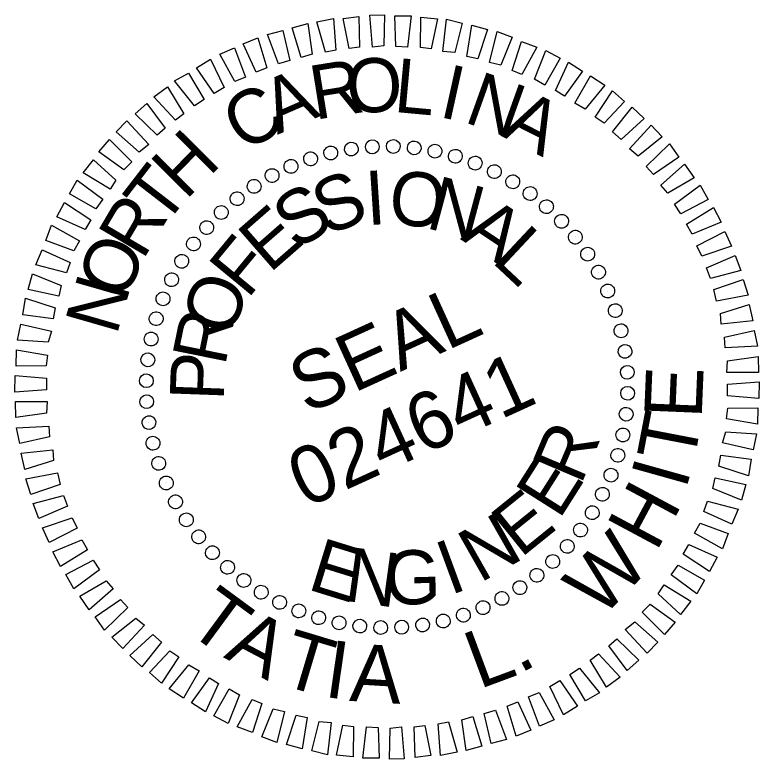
# Model space of a CAD drawing. Extents: x 2249019 to 2251039, y 663030 to 664799.
# Drawn here: x 2250809.3 to 2250886.9, y 664679.9 to 664757.5 of the extents above; entities that cross this region are included whole.
import ezdxf

# ---------------------------------------------------------------- set-up
doc = ezdxf.new("R2010")
doc.units = 0
doc.layers.add('Sheet Professional Seal CELL', color=7, linetype='Continuous')

msp = doc.modelspace()

# ---------------------------------------------------------------- linework, layer by layer
at = {"layer": 'Sheet Professional Seal CELL'}
for p, q in [((2250844.359, 664743.503), (2250844.359, 664743.503)), ((2250846.56, 664743.738), (2250846.56, 664743.738)), ((2250848.753, 664743.749), (2250848.753, 664743.749)), ((2250850.942, 664743.648), (2250850.942, 664743.648)), ((2250853.099, 664743.257), (2250853.099, 664743.257)), ((2250840.16, 664742.468), (2250840.16, 664742.468)), ((2250842.261, 664743.042), (2250842.261, 664743.042)), ((2250855.251, 664742.755), (2250855.251, 664742.755)), ((2250838.096, 664741.692), (2250838.096, 664741.692)), ((2250857.284, 664742.033), (2250857.284, 664742.033)), ((2250859.333, 664741.154), (2250859.333, 664741.154)), ((2250836.115, 664740.733), (2250836.115, 664740.733)), ((2250834.283, 664739.568), (2250834.283, 664739.568)), ((2250861.196, 664740.081), (2250861.196, 664740.081)), ((2250863.031, 664738.829), (2250863.031, 664738.829)), ((2250832.447, 664738.292), (2250832.447, 664738.292)), ((2250864.75, 664737.47), (2250864.75, 664737.47)), ((2250830.786, 664736.875), (2250830.786, 664736.875)), ((2250866.308, 664735.982), (2250866.308, 664735.982)), ((2250829.298, 664735.317), (2250829.298, 664735.317)), ((2250867.725, 664734.32), (2250867.725, 664734.32)), ((2250827.938, 664733.598), (2250827.938, 664733.598)), ((2250869.001, 664732.484), (2250869.001, 664732.484)), ((2250826.687, 664731.763), (2250826.687, 664731.763)), ((2250870.166, 664730.652), (2250870.166, 664730.652)), ((2250825.613, 664729.9), (2250825.613, 664729.9)), ((2250871.125, 664728.671), (2250871.125, 664728.671)), ((2250824.734, 664727.851), (2250824.734, 664727.851)), ((2250871.901, 664726.607), (2250871.901, 664726.607)), ((2250824.012, 664725.818), (2250824.012, 664725.818)), ((2250872.474, 664724.506), (2250872.474, 664724.506)), ((2250823.51, 664723.666), (2250823.51, 664723.666)), ((2250872.936, 664722.409), (2250872.936, 664722.409)), ((2250823.12, 664721.509), (2250823.12, 664721.509)), ((2250873.171, 664720.207), (2250873.171, 664720.207)), ((2250823.019, 664719.32), (2250823.019, 664719.32)), ((2250848.1, 664718.667), (2250848.1, 664718.667)), ((2250873.182, 664718.014), (2250873.182, 664718.014)), ((2250823.03, 664717.127), (2250823.03, 664717.127)), ((2250873.081, 664715.825), (2250873.081, 664715.825)), ((2250823.264, 664714.926), (2250823.264, 664714.926)), ((2250872.69, 664713.669), (2250872.69, 664713.669)), ((2250823.726, 664712.828), (2250823.726, 664712.828)), ((2250872.188, 664711.516), (2250872.188, 664711.516)), ((2250824.299, 664710.727), (2250824.299, 664710.727)), ((2250871.466, 664709.484), (2250871.466, 664709.484)), ((2250825.076, 664708.663), (2250825.076, 664708.663)), ((2250870.587, 664707.434), (2250870.587, 664707.434)), ((2250826.034, 664706.682), (2250826.034, 664706.682)), ((2250869.514, 664705.571), (2250869.514, 664705.571)), ((2250827.199, 664704.85), (2250827.199, 664704.85)), ((2250868.262, 664703.736), (2250868.262, 664703.736)), ((2250828.476, 664703.014), (2250828.476, 664703.014)), ((2250829.893, 664701.353), (2250829.893, 664701.353)), ((2250866.903, 664702.017), (2250866.903, 664702.017)), ((2250831.45, 664699.865), (2250831.45, 664699.865)), ((2250865.415, 664700.46), (2250865.415, 664700.46)), ((2250863.753, 664699.043), (2250863.753, 664699.043)), ((2250833.169, 664698.505), (2250833.169, 664698.505)), ((2250861.917, 664697.766), (2250861.917, 664697.766)), ((2250835.004, 664697.254), (2250835.004, 664697.254)), ((2250836.867, 664696.18), (2250836.867, 664696.18)), ((2250860.085, 664696.601), (2250860.085, 664696.601)), ((2250838.917, 664695.301), (2250838.917, 664695.301)), ((2250858.104, 664695.643), (2250858.104, 664695.643)), ((2250840.949, 664694.579), (2250840.949, 664694.579)), ((2250856.04, 664694.866), (2250856.04, 664694.866)), ((2250843.102, 664694.077), (2250843.102, 664694.077)), ((2250845.258, 664693.687), (2250845.258, 664693.687)), ((2250849.64, 664693.597), (2250849.64, 664693.597)), ((2250851.842, 664693.831), (2250851.842, 664693.831)), ((2250853.939, 664694.293), (2250853.939, 664694.293)), ((2250847.447, 664693.586), (2250847.447, 664693.586))]:
    msp.add_line(p, q, dxfattribs=at)
for points in [[(2250844.152, 664753.96), (2250843.548, 664757.092), (2250845.166, 664757.28), (2250845.252, 664754.077)], [(2250846.572, 664754.075), (2250846.312, 664757.418), (2250847.835, 664757.453), (2250847.764, 664754.233)], [(2250849.014, 664754.144), (2250848.927, 664757.346), (2250850.628, 664757.353), (2250850.243, 664754.1)], [(2250851.584, 664754.052), (2250851.629, 664757.205), (2250853.347, 664757.054), (2250852.697, 664753.9)], [(2250839.15, 664752.998), (2250838.232, 664756.096), (2250839.837, 664756.553), (2250840.304, 664753.359)], [(2250841.698, 664753.556), (2250840.805, 664756.72), (2250842.518, 664757.061), (2250842.757, 664753.764)], [(2250853.918, 664753.632), (2250854.307, 664756.997), (2250855.925, 664756.581), (2250855.168, 664753.543)], [(2250836.8, 664752.366), (2250835.634, 664755.406), (2250837.26, 664755.818), (2250837.975, 664752.682)], [(2250856.405, 664753.118), (2250856.948, 664756.388), (2250858.587, 664755.926), (2250857.56, 664752.875)], [(2250858.777, 664752.496), (2250859.564, 664755.712), (2250861.154, 664755.118), (2250859.953, 664752.208)], [(2250834.463, 664751.466), (2250833.115, 664754.423), (2250834.637, 664755.062), (2250835.576, 664751.918)], [(2250861.141, 664751.65), (2250862.122, 664754.681), (2250863.712, 664754.087), (2250862.155, 664751.234)], [(2250832.259, 664750.515), (2250830.683, 664753.369), (2250832.205, 664754.008), (2250833.372, 664750.968)], [(2250863.48, 664750.739), (2250864.639, 664753.74), (2250866.155, 664752.947), (2250864.532, 664750.119)], [(2250830.088, 664749.251), (2250828.26, 664751.934), (2250829.724, 664752.821), (2250831.118, 664749.885)], [(2250865.654, 664749.587), (2250867.012, 664752.514), (2250868.478, 664751.589), (2250866.594, 664748.971)], [(2250828.029, 664747.982), (2250825.973, 664750.562), (2250827.412, 664751.383), (2250829.058, 664748.616)], [(2250867.687, 664748.261), (2250869.31, 664751.089), (2250870.797, 664750.118), (2250868.739, 664747.641)], [(2250826.073, 664746.486), (2250823.811, 664748.916), (2250825.213, 664749.94), (2250826.925, 664747.149)], [(2250869.783, 664746.799), (2250871.605, 664749.553), (2250872.839, 664748.412), (2250870.723, 664746.183)], [(2250824.159, 664744.899), (2250821.868, 664747.151), (2250823.092, 664748.204), (2250824.969, 664745.653)], [(2250871.585, 664745.257), (2250873.647, 664747.846), (2250874.902, 664746.66), (2250872.496, 664744.464)], [(2250822.262, 664743.154), (2250819.876, 664745.254), (2250820.992, 664746.422), (2250823.275, 664743.946)], [(2250873.379, 664743.492), (2250875.614, 664745.941), (2250876.758, 664744.759), (2250874.269, 664742.744)], [(2250820.696, 664741.286), (2250818.078, 664743.17), (2250819.198, 664744.45), (2250821.51, 664742.152)], [(2250875.102, 664741.641), (2250877.537, 664744.015), (2250878.494, 664742.638), (2250875.856, 664740.83)], [(2250819.238, 664739.302), (2250816.434, 664740.991), (2250817.513, 664742.362), (2250819.853, 664740.242)], [(2250876.644, 664739.706), (2250879.116, 664741.877), (2250880.094, 664740.455), (2250877.353, 664738.875)], [(2250817.754, 664737.252), (2250815.013, 664738.805), (2250815.802, 664740.209), (2250818.506, 664738.254)], [(2250878.049, 664737.709), (2250880.716, 664739.694), (2250881.558, 664738.21), (2250878.729, 664736.7)], [(2250816.648, 664735.099), (2250813.696, 664736.391), (2250814.489, 664737.906), (2250817.243, 664736.085)], [(2250879.318, 664735.65), (2250882.109, 664737.362), (2250882.905, 664735.857), (2250879.907, 664734.599)], [(2250815.471, 664732.859), (2250812.557, 664733.948), (2250813.151, 664735.538), (2250816.045, 664733.89)], [(2250880.401, 664733.396), (2250883.295, 664734.881), (2250884.001, 664733.334), (2250880.898, 664732.304)], [(2250814.696, 664730.582), (2250811.525, 664731.389), (2250812.186, 664732.954), (2250815.092, 664731.642)], [(2250881.392, 664731.1), (2250884.391, 664732.358), (2250884.984, 664730.815), (2250881.799, 664729.967)], [(2250813.892, 664728.127), (2250810.717, 664728.823), (2250811.179, 664730.462), (2250814.156, 664729.237)], [(2250882.161, 664728.813), (2250885.197, 664729.868), (2250885.72, 664728.238), (2250882.431, 664727.617)], [(2250813.316, 664725.776), (2250810.154, 664726.203), (2250810.416, 664727.916), (2250813.513, 664726.91)], [(2250882.855, 664726.327), (2250885.841, 664727.249), (2250886.228, 664725.557), (2250882.926, 664725.205)], [(2250812.781, 664723.334), (2250809.611, 664723.537), (2250809.94, 664725.226), (2250813.135, 664724.485)], [(2250883.259, 664723.873), (2250886.349, 664724.568), (2250886.715, 664722.922), (2250883.331, 664722.752)], [(2250812.581, 664720.88), (2250809.469, 664720.835), (2250809.508, 664722.556), (2250812.733, 664721.993)], [(2250883.572, 664721.379), (2250886.766, 664721.846), (2250886.818, 664720.166), (2250883.507, 664720.195)], [(2250812.625, 664718.372), (2250809.327, 664718.133), (2250809.367, 664719.854), (2250812.624, 664719.581)], [(2250883.575, 664718.962), (2250886.873, 664719.202), (2250886.834, 664717.48), (2250883.577, 664717.754)], [(2250812.628, 664715.956), (2250809.434, 664715.489), (2250809.382, 664717.169), (2250812.693, 664717.139)], [(2250883.619, 664716.454), (2250886.731, 664716.499), (2250886.692, 664714.778), (2250883.468, 664715.341)], [(2250812.941, 664713.461), (2250809.851, 664712.766), (2250809.485, 664714.413), (2250812.87, 664714.582)], [(2250883.42, 664714), (2250886.59, 664713.797), (2250886.261, 664712.108), (2250883.065, 664712.849)], [(2250813.346, 664711.008), (2250810.359, 664710.085), (2250809.972, 664711.777), (2250813.274, 664712.129)], [(2250882.885, 664711.558), (2250886.047, 664711.132), (2250885.784, 664709.418), (2250882.687, 664710.424)], [(2250814.04, 664708.522), (2250811.004, 664707.467), (2250810.48, 664709.097), (2250813.769, 664709.717)], [(2250882.308, 664709.207), (2250885.483, 664708.512), (2250885.021, 664706.872), (2250882.045, 664708.098)], [(2250814.808, 664706.234), (2250811.809, 664704.977), (2250811.216, 664706.519), (2250814.401, 664707.367)], [(2250881.504, 664706.752), (2250884.675, 664705.945), (2250884.015, 664704.38), (2250881.108, 664705.692)], [(2250815.8, 664703.939), (2250812.905, 664702.454), (2250812.199, 664704.001), (2250815.302, 664705.031)], [(2250880.729, 664704.475), (2250883.643, 664703.386), (2250883.049, 664701.797), (2250880.155, 664703.444)], [(2250816.882, 664701.685), (2250814.091, 664699.972), (2250813.295, 664701.478), (2250816.294, 664702.735)], [(2250879.552, 664702.235), (2250882.504, 664700.944), (2250881.711, 664699.428), (2250878.958, 664701.25)], [(2250818.151, 664699.625), (2250815.484, 664697.64), (2250814.643, 664699.125), (2250817.471, 664700.634)], [(2250878.446, 664700.082), (2250881.187, 664698.53), (2250880.398, 664697.126), (2250877.694, 664699.08)], [(2250819.556, 664697.629), (2250817.084, 664695.457), (2250816.106, 664696.88), (2250818.848, 664698.459)], [(2250876.963, 664698.032), (2250879.766, 664696.343), (2250878.688, 664694.972), (2250876.347, 664697.092)], [(2250821.098, 664695.694), (2250818.663, 664693.32), (2250817.706, 664694.697), (2250820.344, 664696.504)], [(2250875.504, 664696.048), (2250878.122, 664694.164), (2250877.002, 664692.884), (2250874.69, 664695.182)], [(2250822.822, 664693.842), (2250820.586, 664691.394), (2250819.442, 664692.576), (2250821.931, 664694.59)], [(2250873.938, 664694.18), (2250876.324, 664692.081), (2250875.208, 664690.913), (2250872.925, 664693.389)], [(2250824.615, 664692.077), (2250822.554, 664689.488), (2250821.298, 664690.675), (2250823.704, 664692.871)], [(2250872.041, 664692.436), (2250874.332, 664690.183), (2250873.108, 664689.131), (2250871.231, 664691.682)], [(2250826.417, 664690.536), (2250824.596, 664687.782), (2250823.361, 664688.922), (2250825.477, 664691.151)], [(2250870.127, 664690.849), (2250872.389, 664688.418), (2250870.988, 664687.394), (2250869.275, 664690.186)], [(2250828.513, 664689.073), (2250826.89, 664686.245), (2250825.403, 664687.216), (2250827.461, 664689.693)], [(2250868.171, 664689.352), (2250870.227, 664686.773), (2250868.788, 664685.952), (2250867.142, 664688.718)], [(2250830.546, 664687.748), (2250829.188, 664684.82), (2250827.722, 664685.746), (2250829.606, 664688.363)], [(2250866.112, 664688.084), (2250867.94, 664685.4), (2250866.476, 664684.513), (2250865.083, 664687.449)], [(2250832.72, 664686.596), (2250831.561, 664683.594), (2250830.045, 664684.387), (2250831.668, 664687.215)], [(2250863.941, 664686.819), (2250865.517, 664683.966), (2250863.995, 664683.327), (2250862.829, 664686.367)], [(2250835.059, 664685.684), (2250834.078, 664682.654), (2250832.488, 664683.248), (2250834.045, 664686.101)], [(2250861.737, 664685.869), (2250863.085, 664682.912), (2250861.563, 664682.273), (2250860.624, 664685.416)], [(2250837.423, 664684.838), (2250836.636, 664681.622), (2250835.047, 664682.216), (2250836.247, 664685.127)], [(2250839.795, 664684.216), (2250839.252, 664680.947), (2250837.613, 664681.408), (2250838.64, 664684.459)], [(2250857.05, 664684.336), (2250857.968, 664681.238), (2250856.363, 664680.781), (2250855.896, 664683.975)], [(2250859.4, 664684.968), (2250860.566, 664681.928), (2250858.941, 664681.516), (2250858.225, 664684.652)], [(2250842.282, 664683.702), (2250841.893, 664680.337), (2250840.275, 664680.753), (2250841.033, 664683.792)], [(2250854.502, 664683.779), (2250855.395, 664680.614), (2250853.683, 664680.273), (2250853.443, 664683.571)], [(2250844.617, 664683.283), (2250844.571, 664680.13), (2250842.853, 664680.281), (2250843.503, 664683.435)], [(2250847.187, 664683.191), (2250847.273, 664679.988), (2250845.572, 664679.982), (2250845.957, 664683.235)], [(2250849.628, 664683.26), (2250849.888, 664679.917), (2250848.366, 664679.882), (2250848.436, 664683.101)], [(2250852.049, 664683.374), (2250852.652, 664680.243), (2250851.035, 664680.055), (2250850.948, 664683.257)]]:
    msp.add_lwpolyline(points, close=True, dxfattribs=at)
for centre, major_axis in [((2250844.388, 664743.471), (-0.107, 0.712)), ((2250846.564, 664743.7), (-0.044, 0.719)), ((2250848.751, 664743.739), (0.019, 0.72)), ((2250850.934, 664743.587), (0.081, 0.715)), ((2250853.095, 664743.245), (0.143, 0.706)), ((2250840.137, 664742.449), (-0.229, 0.683)), ((2250842.24, 664743.053), (-0.168, 0.7)), ((2250855.218, 664742.716), (0.204, 0.69)), ((2250838.095, 664741.665), (-0.287, 0.66)), ((2250857.287, 664742.004), (0.264, 0.67)), ((2250859.286, 664741.115), (0.321, 0.644)), ((2250836.128, 664740.705), (-0.344, 0.633)), ((2250834.253, 664739.578), (-0.398, 0.6)), ((2250861.2, 664740.054), (0.376, 0.614)), ((2250863.014, 664738.831), (0.428, 0.579)), ((2250832.483, 664738.292), (-0.448, 0.563)), ((2250864.715, 664737.455), (0.477, 0.539)), ((2250830.832, 664736.856), (-0.496, 0.522)), ((2250866.289, 664735.935), (0.522, 0.496)), ((2250829.313, 664735.282), (-0.539, 0.477)), ((2250867.725, 664734.284), (0.563, 0.448)), ((2250827.936, 664733.581), (-0.579, 0.428)), ((2250869.011, 664732.514), (0.6, 0.398)), ((2250826.713, 664731.767), (-0.614, 0.376)), ((2250870.138, 664730.639), (0.633, 0.344)), ((2250825.653, 664729.853), (-0.644, 0.321)), ((2250871.098, 664728.673), (0.66, 0.287)), ((2250824.763, 664727.854), (-0.67, 0.264)), ((2250871.882, 664726.63), (0.683, 0.229)), ((2250824.051, 664725.785), (-0.69, 0.204)), ((2250872.486, 664724.527), (0.7, 0.168)), ((2250823.523, 664723.662), (-0.706, 0.143)), ((2250872.904, 664722.38), (0.712, 0.107)), ((2250823.181, 664721.501), (-0.715, 0.081)), ((2250873.133, 664720.204), (0.719, 0.044)), ((2250823.029, 664719.318), (-0.72, 0.019)), ((2250873.172, 664718.016), (0.72, -0.019)), ((2250823.067, 664717.131), (-0.719, -0.044)), ((2250873.02, 664715.833), (0.715, -0.081)), ((2250823.296, 664714.955), (-0.712, -0.107)), ((2250872.678, 664713.672), (0.706, -0.143)), ((2250823.714, 664712.807), (-0.7, -0.168)), ((2250872.149, 664711.549), (0.69, -0.204)), ((2250824.318, 664710.704), (-0.683, -0.229)), ((2250871.437, 664709.48), (0.67, -0.264)), ((2250825.102, 664708.662), (-0.66, -0.287)), ((2250870.547, 664707.481), (0.644, -0.321)), ((2250826.062, 664706.695), (-0.633, -0.344)), ((2250869.487, 664705.567), (0.614, -0.376)), ((2250827.189, 664704.82), (-0.6, -0.398)), ((2250868.264, 664703.753), (0.579, -0.428)), ((2250828.476, 664703.05), (-0.563, -0.448)), ((2250829.911, 664701.399), (-0.522, -0.496)), ((2250866.887, 664702.053), (0.539, -0.477)), ((2250831.486, 664699.88), (-0.477, -0.539)), ((2250865.368, 664700.478), (0.496, -0.522)), ((2250863.717, 664699.043), (0.448, -0.563)), ((2250833.186, 664698.503), (-0.428, -0.579)), ((2250861.947, 664697.756), (0.398, -0.6)), ((2250835, 664697.28), (-0.376, -0.614)), ((2250836.914, 664696.22), (-0.321, -0.644)), ((2250860.072, 664696.629), (0.344, -0.633)), ((2250838.913, 664695.33), (-0.264, -0.67)), ((2250858.106, 664695.669), (0.287, -0.66)), ((2250840.982, 664694.618), (-0.204, -0.69)), ((2250856.063, 664694.885), (0.229, -0.683)), ((2250843.105, 664694.09), (-0.143, -0.706)), ((2250845.266, 664693.748), (-0.081, -0.715)), ((2250849.637, 664693.634), (0.044, -0.719)), ((2250851.812, 664693.863), (0.107, -0.712)), ((2250853.96, 664694.281), (0.168, -0.7)), ((2250847.449, 664693.596), (-0.019, -0.72))]:
    msp.add_ellipse(centre, major_axis=major_axis, ratio=0.999708, dxfattribs=at)

# ---------------------------------------------------------------- texts
for s, height, rotation, p in [('R', 5.638, 9.13336, (2250840.573, 664746.503)), ('O', 5.638, 1.93343, (2250843.932, 664747.211)), ('L', 5.638, 354.73314, (2250848.703, 664747.353)), ('I', 5.638, 347.5324, (2250853.384, 664746.849)), ('A', 5.638, 23.53258, (2250836.669, 664744.942)), ('N', 5.639, 340.33117, (2250855.983, 664746.331)), ('C', 5.638, 30.73213, (2250833.199, 664743.031)), ('A', 5.639, 333.12941, (2250859.891, 664744.871)), ('H', 5.638, 45.13174, (2250827.114, 664738.058)), ('T', 5.638, 52.33203, (2250824.841, 664735.208)), ('S', 5.638, 22.41266, (2250841.816, 664734.376)), ('I', 5.638, 3.70186, (2250846.019, 664735.523)), ('O', 5.638, 354.34574, (2250848.129, 664735.716)), ('N', 5.638, 344.98887, (2250852.007, 664735.286)), ('S', 5.638, 31.76787, (2250838.562, 664732.837)), ('R', 5.638, 59.53277, (2250822.66, 664731.796)), ('E', 5.638, 41.12333, (2250835.858, 664730.45)), ('A', 5.639, 326.27253, (2250855.679, 664734.103)), ('L', 5.639, 316.91311, (2250858.885, 664731.773)), ('O', 5.638, 66.734, (2250820.807, 664727.544)), ('F', 5.638, 50.47929, (2250833.569, 664727.758)), ('N', 5.639, 73.93576, (2250819.918, 664723.951)), ('O', 5.639, 69.1935, (2250831.79, 664723.704)), ('SEAL', 5.9982, 24.51226, (2250839.742, 664715.789)), ('R', 5.639, 78.55191, (2250831.214, 664720.749)), ('P', 5.639, 87.91115, (2250831.086, 664717.174)), ('024641', 5.9982, 24.51226, (2250839.621, 664705.999)), ('E', 5.998, 87.63115, (2250880.88, 664715.31)), ('T', 5.998, 79.10933, (2250880.02, 664710.489)), ('R', 5.639, 66.99367, (2250868.294, 664708.367)), ('E', 5.638, 57.63635, (2250866.039, 664704.756)), ('I', 5.998, 74.34486, (2250879.231, 664707.866)), ('H', 5.998, 61.83328, (2250876.152, 664701.379)), ('E', 5.638, 38.92402, (2250862.025, 664700.783)), ('N', 5.638, 29.56865, (2250857.77, 664698.183)), ('W', 5.998, 46.12601, (2250870.424, 664694.43)), ('E', 5.638, 342.78915, (2250839.671, 664697.624)), ('I', 5.638, 20.21346, (2250854.66, 664696.93)), ('N', 5.638, 352.14622, (2250843.521, 664696.412)), ('G', 5.638, 1.5025, (2250847.912, 664695.941)), ('T', 5.998, 323.6774, (2250827.007, 664693.352)), ('A', 5.998, 332.19922, (2250830.991, 664690.506)), ('T', 5.998, 343.27759, (2250836.721, 664687.743)), ('L', 5.998, 20.42498, (2250857.704, 664687.147)), ('I', 5.998, 351.79941, (2250841.429, 664686.398)), ('A', 5.998, 356.56388, (2250844.133, 664685.956)), ('.', 5.998, 28.28829, (2250861.926, 664688.757))]:
    msp.add_text(s, height=height, rotation=rotation, dxfattribs=at).set_placement(p)

doc.saveas('drawing.dxf')
